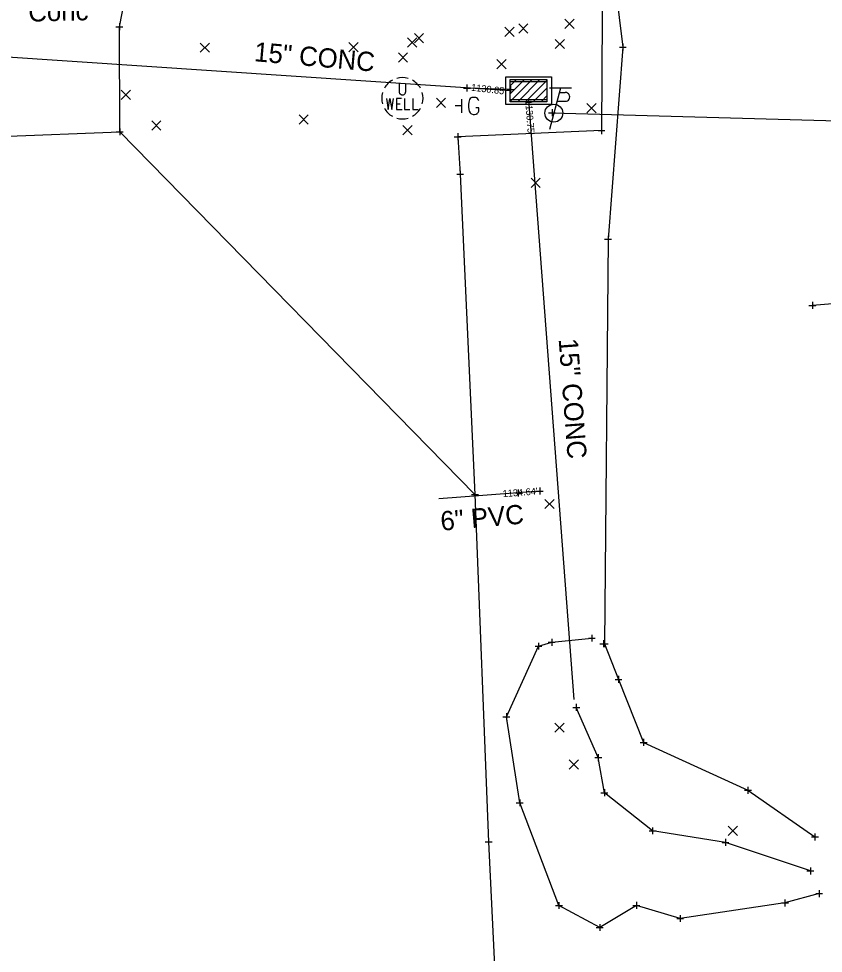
# Model space of a CAD drawing. Extents: x 146022 to 147632, y 437624 to 440659.
# Drawn here: x 146801.3 to 146918.2, y 438466 to 438601.8 of the extents above; entities that cross this region are included whole.
import ezdxf

# ---------------------------------------------------------------- set-up
doc = ezdxf.new("R2010")
doc.units = 0
for name, color, linetype in [('_CIVIL_CONSTRUCTION', 7, 'Continuous'), ('BR_P_Rail_Object', 7, 'Continuous'), ('DR_X_Storm_Sewer', 7, 'Continuous'), ('DR_X_Text', 7, 'Continuous'), ('DT_X_Contour_Major', 7, 'Continuous'), ('DT_X_Island', 7, 'Continuous'), ('DT_X_Triangles', 7, 'Continuous'), ('GE_P_Alignment_100_Distances', 7, 'Continuous'), ('PF_X_Ground_Line', 7, 'Continuous'), ('RD_P_Anchor_Assembly', 7, 'Continuous'), ('RD_P_Fence', 7, 'Continuous'), ('SC_Scratch1', 7, 'Continuous'), ('SV_X_Terrain_Boundary', 7, 'Continuous'), ('UT_X_Electric', 7, 'Continuous'), ('UT_X_Gas', 7, 'Continuous'), ('UT_X_Overhead_Electric', 7, 'Continuous')]:
    doc.layers.add(name, color=color, linetype=linetype)

msp = doc.modelspace()

# ---------------------------------------------------------------- linework, layer by layer
at = {"layer": '_CIVIL_CONSTRUCTION'}
for p, q in [((146871.95, 438599.23), (146873.28, 438600.57)), ((146871.95, 438600.57), (146873.28, 438599.23)), ((146873.95, 438599.73), (146875.28, 438601.07)), ((146873.95, 438601.07), (146875.28, 438599.73)), ((146880.65, 438600.41), (146881.99, 438601.74)), ((146880.65, 438601.74), (146881.99, 438600.41)), ((146858.79, 438598.33), (146860.12, 438599.67)), ((146858.79, 438599.67), (146860.12, 438598.33)), ((146827.66, 438596.95), (146828.99, 438598.28)), ((146827.66, 438598.28), (146828.99, 438596.95)), ((146849.27, 438597.01), (146850.61, 438598.35)), ((146849.27, 438598.35), (146850.61, 438597.01)), ((146857.79, 438597.68), (146859.12, 438599.02)), ((146857.79, 438599.02), (146859.12, 438597.68)), ((146879.26, 438597.48), (146880.59, 438598.82)), ((146879.26, 438598.82), (146880.59, 438597.48)), ((146856.45, 438595.51), (146857.78, 438596.84)), ((146856.45, 438596.84), (146857.78, 438595.51)), ((146870.79, 438594.54), (146872.13, 438595.88)), ((146870.79, 438595.88), (146872.13, 438594.54)), ((146816.17, 438590.09), (146817.5, 438591.42)), ((146816.17, 438591.42), (146817.5, 438590.09)), ((146862, 438588.93), (146863.33, 438590.27)), ((146862, 438590.27), (146863.33, 438588.93)), ((146883.86, 438588.16), (146885.19, 438589.5)), ((146883.86, 438589.5), (146885.19, 438588.16)), ((146820.6, 438585.62), (146821.93, 438586.96)), ((146820.6, 438586.96), (146821.93, 438585.62)), ((146842.02, 438586.51), (146843.36, 438587.85)), ((146842.02, 438587.85), (146843.36, 438586.51)), ((146857.11, 438584.95), (146858.45, 438586.28)), ((146857.11, 438586.28), (146858.45, 438584.95)), ((146875.75, 438577.31), (146877.09, 438578.65)), ((146875.75, 438578.65), (146877.09, 438577.31)), ((146877.76, 438530.64), (146879.1, 438531.97)), ((146877.76, 438531.97), (146879.1, 438530.64)), ((146879.21, 438498.11), (146880.54, 438499.45)), ((146879.21, 438499.45), (146880.54, 438498.11)), ((146881.3, 438492.76), (146882.63, 438494.1)), ((146881.3, 438494.1), (146882.63, 438492.76)), ((146904.4, 438483.12), (146905.73, 438484.45)), ((146904.4, 438484.45), (146905.73, 438483.12))]:
    msp.add_line(p, q, dxfattribs=at)
at = {"layer": 'BR_P_Rail_Object'}
for points in [[(146886.14, 438610.59), (146885.99, 438585.55), (146865.09, 438584.67)], [(146865.09, 438584.67), (146865.43, 438579.22), (146867.59, 438532.67), (146869.58, 438482.2), (146870.46, 438463.14), (146873.4, 438373.87), (146876.91, 438274.25), (146880.85, 438170.02)]]:
    msp.add_lwpolyline(points, dxfattribs=at)
at = {"layer": 'DR_X_Storm_Sewer'}
for p, q in [((146872.73, 438591.35), (146787.94, 438597.01)), ((146875.39, 438590.01), (146881.98, 438502.9)), ((146877, 438533.18), (146862.35, 438532.02))]:
    msp.add_line(p, q, dxfattribs=at)
at = {"layer": 'DT_X_Contour_Major'}
for p, q in [((146881.62, 438591.7), (146878.42, 438591.7)), ((146880.02, 438591.7), (146878.42, 438585.7)), ((146879.86, 438591.1), (146880.71, 438591.1)), ((146879.52, 438589.83), (146880.71, 438589.83))]:
    msp.add_line(p, q, dxfattribs=at)
msp.add_circle((146879.06, 438588.1), 1.3, dxfattribs=at)
msp.add_arc((146880.72, 438590.46), 0.638, 268.8767, 91.1233, dxfattribs=at)
at = {"layer": 'DT_X_Island'}
for p, q in [((146865.66, 438588.14), (146865.66, 438590.14)), ((146865.66, 438589.14), (146864.71, 438589.14))]:
    msp.add_line(p, q, dxfattribs=at)
msp.add_lwpolyline([(146868.14, 438589.9), (146868.12, 438590), (146868.06, 438590.1), (146867.96, 438590.2), (146867.82, 438590.31), (146867.72, 438590.35), (146867.65, 438590.37), (146867.53, 438590.39), (146867.29, 438590.39), (146867.19, 438590.37), (146867.13, 438590.35), (146867.06, 438590.31), (146866.9, 438590.2), (146866.8, 438590.06), (146866.74, 438589.9), (146866.7, 438589.68), (146866.66, 438589.37), (146866.66, 438588.96), (146866.68, 438588.62), (146866.76, 438588.37), (146866.88, 438588.13), (146866.98, 438588.05), (146867.09, 438587.97), (146867.31, 438587.89), (146867.53, 438587.89), (146867.74, 438587.93), (146867.82, 438587.97), (146867.9, 438588.01), (146867.98, 438588.09), (146868.06, 438588.21), (146868.14, 438588.38), (146868.14, 438588.88), (146867.72, 438588.88)], dxfattribs=at)
at = {"layer": 'DT_X_Triangles'}
for p, q in [((146875.39, 438593.35), (146875.39, 438593.35)), ((146875.39, 438592.68), (146875.39, 438592.68)), ((146872.73, 438591.35), (146872.73, 438591.35)), ((146875.39, 438591.35), (146875.39, 438591.35)), ((146875.39, 438591.35), (146875.39, 438591.35)), ((146878.06, 438591.35), (146878.06, 438591.35)), ((146875.39, 438590.01), (146875.39, 438590.01)), ((146875.39, 438589.73), (146875.39, 438589.73)), ((146875.39, 438589.35), (146875.39, 438589.35))]:
    msp.add_line(p, q, dxfattribs=at)
at = {"layer": 'GE_P_Alignment_100_Distances'}
msp.add_lwpolyline([(146878.79, 438588.15), (147008.47, 438584.5), (147008.59, 438584.46), (147110.26, 438581.75)], dxfattribs=at)
at = {"layer": 'PF_X_Ground_Line'}
for points in [[(146889.72, 438610.79), (146887.52, 438610.3), (146889.09, 438597.69), (146886.94, 438569.76), (146886.43, 438510.99), (146888.46, 438505.81), (146892.11, 438496.65), (146907.27, 438489.69), (146917.01, 438482.91)], [(146944.2, 438145.61), (146942.51, 438206.23), (146939.98, 438265.94), (146939.05, 438324.76), (146936.01, 438383.62), (146934.98, 438441.73), (146931.66, 438500.39), (146928.09, 438553.7), (146926.58, 438560.96), (146916.64, 438560.16)], [(146917.62, 438474.67), (146912.65, 438473.32), (146897.42, 438471.06), (146891.05, 438472.96), (146885.73, 438469.75), (146879.8, 438472.94), (146874.1, 438487.87), (146872.15, 438500.38), (146876.82, 438510.63), (146878.74, 438511.2), (146884.58, 438511.8)]]:
    msp.add_lwpolyline(points, dxfattribs=at)
at = {"layer": 'RD_P_Anchor_Assembly'}
for p, q in [((146815.4, 438600.66), (146816.4, 438600.66)), ((146815.9, 438601.16), (146815.9, 438600.16)), ((146815.9, 438600.66), (146815.9, 438600.66)), ((146889.09, 438598.19), (146889.09, 438597.19)), ((146888.59, 438597.69), (146889.59, 438597.69)), ((146889.09, 438597.69), (146889.09, 438597.69)), ((146865.93, 438591.74), (146866.93, 438591.74)), ((146866.43, 438592.24), (146866.43, 438591.24)), ((146866.43, 438591.74), (146866.43, 438591.74)), ((146872.27, 438591.53), (146873.27, 438591.53)), ((146872.77, 438592.03), (146872.77, 438591.03)), ((146872.77, 438591.53), (146872.77, 438591.53)), ((146878.79, 438588.65), (146878.79, 438587.65)), ((146878.29, 438588.15), (146879.29, 438588.15)), ((146878.79, 438588.15), (146878.79, 438588.15)), ((146815.95, 438585.88), (146815.95, 438584.88)), ((146885.99, 438586.05), (146885.99, 438585.05)), ((146815.45, 438585.38), (146816.45, 438585.38)), ((146815.95, 438585.38), (146815.95, 438585.38)), ((146864.59, 438584.67), (146865.59, 438584.67)), ((146865.09, 438585.17), (146865.09, 438584.17)), ((146865.09, 438584.67), (146865.09, 438584.67)), ((146885.49, 438585.55), (146886.49, 438585.55)), ((146885.99, 438585.55), (146885.99, 438585.55)), ((146864.93, 438579.22), (146865.93, 438579.22)), ((146865.43, 438579.72), (146865.43, 438578.72)), ((146865.43, 438579.22), (146865.43, 438579.22)), ((146886.44, 438569.76), (146887.44, 438569.76)), ((146886.94, 438570.26), (146886.94, 438569.26)), ((146886.94, 438569.76), (146886.94, 438569.76)), ((146916.14, 438560.16), (146917.14, 438560.16)), ((146916.64, 438560.66), (146916.64, 438559.66)), ((146916.64, 438560.16), (146916.64, 438560.16)), ((146867.09, 438532.67), (146868.09, 438532.67)), ((146867.59, 438533.17), (146867.59, 438532.17)), ((146867.59, 438532.67), (146867.59, 438532.67)), ((146884.58, 438512.3), (146884.58, 438511.3)), ((146876.82, 438511.13), (146876.82, 438510.13)), ((146878.24, 438511.2), (146879.24, 438511.2)), ((146878.74, 438511.7), (146878.74, 438510.7)), ((146878.74, 438511.2), (146878.74, 438511.2)), ((146884.08, 438511.8), (146885.08, 438511.8)), ((146884.58, 438511.8), (146884.58, 438511.8)), ((146885.76, 438510.99), (146886.76, 438510.99)), ((146885.93, 438510.99), (146886.93, 438510.99)), ((146886.26, 438511.49), (146886.26, 438510.49)), ((146886.26, 438510.99), (146886.26, 438510.99)), ((146886.43, 438511.49), (146886.43, 438510.49)), ((146886.43, 438510.99), (146886.43, 438510.99)), ((146876.32, 438510.63), (146877.32, 438510.63)), ((146876.82, 438510.63), (146876.82, 438510.63)), ((146887.96, 438505.81), (146888.96, 438505.81)), ((146888.46, 438506.31), (146888.46, 438505.31)), ((146888.46, 438505.81), (146888.46, 438505.81)), ((146881.81, 438501.74), (146882.81, 438501.74)), ((146882.31, 438502.24), (146882.31, 438501.24)), ((146882.31, 438501.74), (146882.31, 438501.74)), ((146871.65, 438500.38), (146872.65, 438500.38)), ((146872.15, 438500.88), (146872.15, 438499.88)), ((146872.15, 438500.38), (146872.15, 438500.38)), ((146891.61, 438496.65), (146892.61, 438496.65)), ((146892.11, 438497.15), (146892.11, 438496.15)), ((146892.11, 438496.65), (146892.11, 438496.65)), ((146885.51, 438494.94), (146885.51, 438493.94)), ((146885.01, 438494.44), (146886.01, 438494.44)), ((146885.51, 438494.44), (146885.51, 438494.44)), ((146885.9, 438489.33), (146886.9, 438489.33)), ((146886.4, 438489.83), (146886.4, 438488.83)), ((146886.4, 438489.33), (146886.4, 438489.33)), ((146906.77, 438489.69), (146907.77, 438489.69)), ((146907.27, 438490.19), (146907.27, 438489.19)), ((146907.27, 438489.69), (146907.27, 438489.69)), ((146873.6, 438487.87), (146874.6, 438487.87)), ((146874.1, 438488.37), (146874.1, 438487.37)), ((146874.1, 438487.87), (146874.1, 438487.87)), ((146892.91, 438483.8), (146893.91, 438483.8)), ((146893.41, 438484.3), (146893.41, 438483.3)), ((146893.41, 438483.8), (146893.41, 438483.8)), ((146869.58, 438482.7), (146869.58, 438481.7)), ((146904, 438482.62), (146904, 438481.62)), ((146916.51, 438482.91), (146917.51, 438482.91)), ((146917.01, 438483.41), (146917.01, 438482.41)), ((146917.01, 438482.91), (146917.01, 438482.91)), ((146869.08, 438482.2), (146870.08, 438482.2)), ((146869.58, 438482.2), (146869.58, 438482.2)), ((146903.5, 438482.12), (146904.5, 438482.12)), ((146904, 438482.12), (146904, 438482.12)), ((146916.35, 438478.47), (146916.35, 438477.47)), ((146915.85, 438477.97), (146916.85, 438477.97)), ((146916.35, 438477.97), (146916.35, 438477.97)), ((146917.12, 438474.67), (146918.12, 438474.67)), ((146917.62, 438475.17), (146917.62, 438474.17)), ((146917.62, 438474.67), (146917.62, 438474.67)), ((146879.3, 438472.94), (146880.3, 438472.94)), ((146879.8, 438473.44), (146879.8, 438472.44)), ((146879.8, 438472.94), (146879.8, 438472.94)), ((146890.55, 438472.96), (146891.55, 438472.96)), ((146891.05, 438473.46), (146891.05, 438472.46)), ((146891.05, 438472.96), (146891.05, 438472.96)), ((146912.15, 438473.32), (146913.15, 438473.32)), ((146912.65, 438473.82), (146912.65, 438472.82)), ((146912.65, 438473.32), (146912.65, 438473.32)), ((146897.42, 438471.56), (146897.42, 438470.56)), ((146885.73, 438470.25), (146885.73, 438469.25)), ((146896.92, 438471.06), (146897.92, 438471.06)), ((146897.42, 438471.06), (146897.42, 438471.06)), ((146885.23, 438469.75), (146886.23, 438469.75)), ((146885.73, 438469.75), (146885.73, 438469.75))]:
    msp.add_line(p, q, dxfattribs=at)
at = {"layer": 'RD_P_Fence'}
for points in [[(146872.77, 438591.53), (146866.43, 438591.74)], [(146916.35, 438477.97), (146904, 438482.12), (146893.41, 438483.8), (146886.4, 438489.33), (146885.51, 438494.44), (146882.31, 438501.74)]]:
    msp.add_lwpolyline(points, dxfattribs=at)
at = {"layer": 'SC_Scratch1'}
msp.add_lwpolyline([(146815.95, 438585.38), (146815.9, 438600.66), (146818.86, 438615.87)], dxfattribs=at)
at = {"layer": 'SV_X_Terrain_Boundary'}
msp.add_lwpolyline([(146798.57, 438584.69), (146815.95, 438585.38), (146867.59, 438532.67), (146869.58, 438482.2), (146870.46, 438463.14)], dxfattribs=at)
at = {"layer": 'UT_X_Electric'}
for p, q in [((146872.73, 438589.78), (146875.91, 438592.96)), ((146872.73, 438590.91), (146874.78, 438592.96)), ((146872.73, 438592.04), (146873.65, 438592.96)), ((146873.81, 438589.73), (146877.04, 438592.96)), ((146874.94, 438589.73), (146878.06, 438592.85)), ((146876.07, 438589.73), (146878.06, 438591.72)), ((146877.21, 438589.73), (146878.06, 438590.59))]:
    msp.add_line(p, q, dxfattribs=at)
for points in [[(146872.06, 438593.35), (146878.73, 438593.35), (146878.73, 438589.35), (146872.06, 438589.35)], [(146872.73, 438592.96), (146878.06, 438592.96), (146878.06, 438589.73), (146872.73, 438589.73)], [(146872.73, 438592.68), (146878.06, 438592.68), (146878.06, 438590.01), (146872.73, 438590.01)]]:
    msp.add_lwpolyline(points, close=True, dxfattribs=at)
at = {"layer": 'UT_X_Gas'}
msp.add_line((146857.04, 438590.26), (146857.04, 438590.26), dxfattribs=at)
for points in [[(146856.56, 438592.35), (146856.56, 438591.23), (146856.58, 438591.12), (146856.59, 438591.08), (146856.61, 438591.01), (146856.64, 438590.96), (146856.68, 438590.91), (146856.7, 438590.89), (146856.71, 438590.88), (146856.77, 438590.84), (146856.8, 438590.81), (146856.85, 438590.79), (146856.93, 438590.76), (146857, 438590.75), (146857.08, 438590.75), (146857.16, 438590.76), (146857.21, 438590.77), (146857.28, 438590.81), (146857.34, 438590.85), (146857.4, 438590.9), (146857.45, 438590.96), (146857.48, 438591.04), (146857.51, 438591.1), (146857.52, 438591.23), (146857.52, 438592.35)], [(146854.75, 438590.23), (146854.96, 438588.63), (146855.23, 438590.23), (146855.51, 438588.63), (146855.73, 438590.23)], [(146856.93, 438590.23), (146856.17, 438590.23), (146856.17, 438588.63), (146856.99, 438588.63)], [(146857.37, 438590.23), (146857.37, 438588.63), (146858.13, 438588.63)], [(146858.57, 438590.23), (146858.57, 438588.63), (146859.34, 438588.63)], [(146856.17, 438589.43), (146856.71, 438589.43)]]:
    msp.add_lwpolyline(points, dxfattribs=at)
for start, end in [(118.9866, 150.9578), (73.9409, 105.9366), (28.9866, 60.9578), (164.0021, 196.0591), (344.0021, 15.9979), (208.9866, 240.9578), (298.9866, 331.0134), (253.9409, 285.9366)]:
    msp.add_arc((146857.04, 438590.26), 3, start, end, dxfattribs=at)
at = {"layer": 'UT_X_Overhead_Electric'}
for p, q in [((146873.39, 438532.9), (146874.39, 438532.9)), ((146873.89, 438533.4), (146873.89, 438532.4)), ((146873.89, 438532.9), (146873.89, 438532.9)), ((146876.5, 438533.18), (146877.5, 438533.18)), ((146877, 438533.68), (146877, 438532.68)), ((146877, 438533.18), (146877, 438533.18))]:
    msp.add_line(p, q, dxfattribs=at)

# ---------------------------------------------------------------- texts
at = {"layer": 'DR_X_Text'}
for s, rotation, p in [('Conc', 1.4771, (146802.69, 438601.38)), ('15" CONC', 355, (146835.41, 438595.65)), ('15" CONC', 274.3256, (146879.75, 438555.26)), ('6" PVC', 5, (146862.69, 438527.4))]:
    msp.add_text(s, height=2.8, rotation=rotation, dxfattribs=at).set_placement(p)
at = {"layer": 'SC_Scratch1'}
for s, rotation, p in [("1130.85'", 353.3057, (146866.99, 438591.37)), ("1130.75'", 274.3256, (146874.89, 438589.98)), ("1134.64'", 4.5169, (146871.66, 438532.28))]:
    msp.add_text(s, height=1, rotation=rotation, dxfattribs=at).set_placement(p)

doc.saveas('drawing.dxf')
